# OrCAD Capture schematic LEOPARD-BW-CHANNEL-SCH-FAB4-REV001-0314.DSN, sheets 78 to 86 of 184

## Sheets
78 103_TPM HEADER: size A3; title: TPM HEADER
79 102_WELLSBURG SPI FLASH: size Custom; title: WELLSBURG SPI FLASH
80 101_miniSAS CONNECTORS_SATA_PWR: size A3; title: MiniSAS CONNECTOR_SATA_PWR
81 098_mSATA CONNECTOR: size A3; title: mSATA CONNECTOR
82 097_SATA CONNECTORS: size A3; title: SATA CONNECTOR
83 096_NGFF CONNECTOR: size Custom; title: NGFF CONNECTOR
84 095_WBG - HEADERS: size A3; title: WBG - HEADERS
85 090_WBG - FILTERING: title: WBG - FILTERING
86 089_WBG - GROUND: size A3; title: WBG - GROUND

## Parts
sheet 083_WBG - DMI & USB
WBG1  WELLSBURG-1-GP-U  [BGA836M25H87]  (sections A,B,C,D,E,F,G,H,I,J,K)
sheet 095_WBG - HEADERS
C272  SC1U10V2KX-4-GP  [C402H22]
C273  SC1U10V2KX-4-GP  [C402H22]
CN47  FCI-CON3-S1-GP  [68001-203HLF]
JP3  FCI-CON3-S1-GP  [68001-203HLF]
JP4  FCI-CON3-S1-GP  [68001-203HLF]
JP6  FCI-CON3-S1-GP  [68001-203HLF]
R233  1KR2F-3-GP  [R402H16]
R234  10KR2F-2-GP  [R402H16]
R236  100R2F-L1-GP-U  [R402H14]
R237  1KR2F-3-GP  [R402H16]
R239  20KR2F-L-GP  [R402H16]
R240  10KR2F-2-GP  [R402H16]
R241  1MR3F-GP  [R603H22]
R242  1KR2F-3-GP  [R402H16]
R243  1KR2F-3-GP  [R402H16]
R244  4K7R2F-GP  [R402H16]
R245  1MR3F-GP  [R603H22]
R246  20KR2F-L-GP  [R402H16]
R260  0R2J-2-GP  [R402H16]
R918  10KR2F-2-GP  [R402H16]
TP191  TPAD24  [TPAD24]
TP283  TPAD24  [TPAD24]
TP284  TPAD24  [TPAD24]
TP315  TPAD24  [TPAD24]
TP316  TPAD24  [TPAD24]
TP317  TPAD24  [TPAD24]
TP318  TPAD24  [TPAD24]
sheet 096_NGFF CONNECTOR
C28  SC1U10V2KX-4-GP  [C402H22]
C29  SC10U6D3V5KX-4GP  [C805H58]
C30  SC1U10V2KX-4-GP  [C402H22]
C85  SC1U10V2KX-4-GP  [C402H22]
C87  SC1U10V2KX-4-GP  [C402H22]
C90  SCD1U16V2KX-3GP  [C402H22]
C91  SCD1U16V2KX-3GP  [C402H22]
C93  SCD1U16V2KX-3GP  [C402H22]
C94  SCD1U16V2KX-3GP  [C402H22]
C103  SCD1U16V2KX-3GP  [C402H22]
C106  SC10U6D3V5KX-4GP  [C805H58]
C757  SCD01U16V2KX-3GP  [C402H22]
C758  SCD01U16V2KX-3GP  [C402H22]
NGFF1  SKT-MINI67P-33-GP  [10128798-004RLF]
R257  0R6J-3-GP  [R1206H28]
R258  0R6J-3-GP  [R1206H28]
R524  0R2J-2-GP  [R402H16]
R530  0R2J-2-GP  [R402H16]
R1041  10KR2F-2-GP  [R402H16]
R1106  0R2J-2-GP  [R402H16]
R1109  0R2J-2-GP  [R402H16]
R1207  0R2J-2-GP  [R402H16]
R1208  0R2J-2-GP  [R402H16]
R1258  0R2J-2-GP  [R402H16]
sheet 097_SATA CONNECTORS
C737  SCD01U16V2KX-3GP  [C402H22]
C738  SCD01U16V2KX-3GP  [C402H22]
C739  SCD01U16V2KX-3GP  [C402H22]
C740  SCD01U16V2KX-3GP  [C402H22]
C798  SC10U16V6KX-2GP  [C1206H71]
C1203  SCD1U16V2KX-3GP  [C402H22]
C1207  SC10U25V6KX-2GP  [C1206H63]
F2  FUSE-3A75V-GP  [FUSE-3216-2H68]
F5  FUSE-3A75V-GP  [FUSE-3216-2H68]
HDPR1  AMP-CON4-S2-GP  [171825-4]
SATA1  SKT-SATA7P-19-GP-U  [ABA-SAT-010-K04-U]
sheet 098_mSATA CONNECTOR
C310  SCD1U16V2KX-3GP  [C402H22]
C311  SCD1U16V2KX-3GP  [C402H22]
C312  SCD1U16V2KX-3GP  [C402H22]
C313  SCD1U16V2KX-3GP  [C402H22]
C753  SCD01U16V2KX-3GP  [C402H22]
C754  SCD01U16V2KX-3GP  [C402H22]
MSATA1  SKT-MINI52P-200-GP  [80003-3023]
R947  0R2J-2-GP  [R402H16]
R1038  0R2J-2-GP  [R402H16]
R1268  0R2J-2-GP  [R402H16]
sheet 101_miniSAS CONNECTORS_SATA_PWR
C1140  E100U16VM-32-GP  [ECAP-100D6D3H237]
C1142  SCD1U16V2KX-3GP  [C402H22]
C1144  SCD1U16V2KX-3GP  [C402H22]
C1145  SCD1U16V2KX-3GP  [C402H22]
C1147  SCD1U16V2KX-3GP  [C402H22]
C1148  E100U16VM-32-GP  [ECAP-100D6D3H237]
C1151  SCD1U16V2KX-3GP  [C402H22]
C1152  SCD1U16V2KX-3GP  [C402H22]
C1154  SCD1U16V2KX-3GP  [C402H22]
C1155  SCD1U16V2KX-3GP  [C402H22]
F3  FUSE-7A32V-GP  [FUSE-3216H43]
F4  FUSE-7A32V-GP  [FUSE-3216H43]
F7  FUSE-20A24V-GP  [FUSE-3216H43]
SASPW1  LOTES-CONN8B-S-GP-U1  [ABA-POW-005-K04-U1]
sheet 102_WELLSBURG SPI FLASH
C27  SCD1U16V2KX-3GP  [C402H22]
C327  SCD1U16V2KX-3GP  [C402H22]
C328  SC1U10V2KX-4-GP  [C402H22]
C357  SCD1U16V2KX-3GP  [C402H22]
C358  SCD1U16V2KX-3GP  [C402H22]
C5695  SCD1U16V2KX-3GP  [C402H22]
R301  0R2J-2-GP  [R402H16]
R304  0R2J-2-GP  [R402H16]
R305  0R2J-2-GP  [R402H16]
R306  0R2J-2-GP  [R402H16]
R307  10KR2F-2-GP  [R402H16]
R308  10KR2F-2-GP  [R402H16]
R309  0R2J-2-GP  [R402H16]
R310  0R2J-2-GP  [R402H16]
R311  0R2J-2-GP  [R402H16]
R312  33R2F-3-GP  [R402H16]
R313  33R2F-3-GP  [R402H16]
R314  1KR2F-L-GP  [R402H16]
R373  0R2J-2-GP  [R402H16]
R375  10KR2F-2-GP  [R402H16]
R376  0R2J-2-GP  [R402H16]
R377  10KR2F-L1-GP  [R402H15]
R412  10KR2F-2-GP  [R402H16]
R414  10KR2F-2-GP  [R402H16]
R427  0R2J-2-GP  [R402H16]
R432  0R2J-2-GP  [R402H16]
R434  2K2R2F-GP  [R402H16]
R464  10KR2F-2-GP  [R402H16]
R466  10KR2F-2-GP  [R402H16]
R500  2K2R2F-GP  [R402H16]
R509  10KR2F-2-GP  [R402H16]
R729  0R2J-2-GP  [R402H16]
R730  0R2J-2-GP  [R402H16]
R772  0R2J-2-GP  [R402H16]
R794  0R2J-2-GP  [R402H16]
R795  0R2J-2-GP  [R402H16]
R800  0R2J-2-GP  [R402H16]
R801  0R2J-2-GP  [R402H16]
R948  2K2R2F-GP  [R402H16]
R5846  220R2J-L2-GP  [R402H16]
SKT2  SKT-SPI16P-GP-U  [SKT-SOIC16-153139H258]
U19  NC7SB3157P6X-2GP  [UMT6H44]
U20  PI3B3257QE-GP  [QSOIC16H69]
U28  W25Q128FVFIG-GP  [SOIC16-6H104]
U106  SNLVC1G125DB-GP  [SOT-23-5H58]
U107  SNLVC1G125DB-GP  [SOT-23-5H58]
sheet 103_TPM HEADER
C31  SCD1U10V2KX-5GP  [C402H22]
C32  SCD1U10V2KX-5GP  [C402H22]
CN3  FCI-CONN15-GP  [91932-31115LF]
R1274  1KR2F-L-GP  [R402H16]
R1275  0R2J-2-GP  [R402H16]

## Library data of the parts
WBG1 = WELLSBURG-1-GP-U: IC PCH WELLSBURG FCBGA 836P(SERVER); GREENDFACTOR: R2_C;; POP?: 071.82029.0B0U; Package Type: ASIC2-G4; Part Number: 71.WSBUG.00U; SPEC: http://wpqssvr.wistron.com.tw:7001/wpqs/servlet/COM.qpart.Attachment?PartNumber=71.WSBUG.00U
C28 C30 C85 C87 C272 C273 C328 = SC1U10V2KX-4-GP: CHIP CAP C 1U 10V K 0402 X6S; GREENDFACTOR: R2_SA;HF_SA;; Part Number: 78.10523.8FL; Part Type: SMD-BCG6; SPEC: http://wpqssvr.wistron.com.tw:7001/wpqs/servlet/COM.qpart.Attachment?PartNumber=78.10523.8FL
CN47 = FCI-CON3-S1-GP: HEAD ML 1R3P ST 68001-203HLF; Category: PCH; GREENDFACTOR: R_SA;; Green Factor: R_SA;; Part Number: 21.61084.103; Part Type: CONN-G4; ROOM: IMMv2; S/D: DIP; SPEC: http://wpqssvr.wistron.com.tw:7001/wpqs/servlet/COM.qpart.Attachment?PartNumber=21.61084.103; Vender: FCI
JP3 JP4 JP6 = FCI-CON3-S1-GP: HEAD ML 1R3P ST 68001-203HLF; GREENDFACTOR: R2_SA;; Part Number: 21.61084.103; Part Type: CONN-G4; SPEC: http://wpqssvr.wistron.com.tw:7001/wpqs/servlet/COM.qpart.Attachment?PartNumber=21.61084.103
R233 R237 R242 = 1KR2F-3-GP: CHIP RES 1K F 1/16W 0402; Category: PCH; GREENDFACTOR: R2_SA;HF_SA;G_SA;; Package Type: SMD-RG; Part Number: 64.10015.6DL; Part Type: SMD-RG; SPEC: http://wpqssvr.wistron.com.tw:7001/wpqs/servlet/COM.qpart.Attachment?PartNumber=64.10015.6DL; VENDORPARTNUMBER: RM04FTN1001 / RTT021001FTH / RR0510S-1001-FN / RC0402FR-071KL/WR04X1001FTL
R234 R240 R307 R308 R375 R412 R414 R509 = 10KR2F-2-GP: CHIP RES 10K F 1/16W 0402; GREENDFACTOR: R2_SA;HF_SA;G_SA;; Part Number: 64.10025.6DL; Part Type: SMD-RG; SPEC: http://wpqssvr.wistron.com.tw:7001/wpqs/servlet/COM.qpart.Attachment?PartNumber=64.10025.6DL
R236 = 100R2F-L1-GP-U: CHIP RES 100 F 1/16W 0402; Category: CPU SIDE BAND; POP?: NOPOP; Part Number: 64.10005.6DL; Part Type: SMD-RG
R239 R246 = 20KR2F-L-GP: CHIP RES 20K F 1/16W 0402; GREENDFACTOR: R2_SA;HF_SA;G_SA;; Package Type: SMD-RG; Part Number: 64.20025.6DL; SPEC: http://wpqssvr.wistron.com.tw:7001/wpqs/servlet/COM.qpart.Attachment?PartNumber=64.20025.6DL
R241 = 1MR3F-GP: CHIP RES 1M F 1/10W 0603(ROHS); Category: PCH; Part Number: 64.10045.55L; Part Type: RCL_GP
R243 = 1KR2F-3-GP: CHIP RES 1K F 1/16W 0402; Category: PCH; GREENDFACTOR: R2_SA;HF_SA;G_SA;; POP?: NOPOP; Package Type: SMD-RG; Part Number: 64.10015.6DL; Part Type: SMD-RG; SPEC: http://wpqssvr.wistron.com.tw:7001/wpqs/servlet/COM.qpart.Attachment?PartNumber=64.10015.6DL; VENDORPARTNUMBER: RM04FTN1001 / RTT021001FTH / RR0510S-1001-FN / RC0402FR-071KL/WR04X1001FTL
R244 = 4K7R2F-GP: CHIP RES 4.7K F 1/16W 0402; Category: PCH; Part Number: 64.47015.6DL; Part Type: RCL_GP
R245 = 1MR3F-GP: CHIP RES 1M F 1/10W 0603(ROHS); Category: PCH; POP?: NOPOP; Part Number: 64.10045.55L; Part Type: RCL_GP
R260 R301 R304-R306 R373 R376 R427 R432 = 0R2J-2-GP: CHIP RES 0 J 1/16W 0402; Category: PCH; DESCRIPTIO: CHIP RES 0 J 1/16W 0402; GREENDFACTOR: R2_SA;HF_SA;G_SA;; POP?: NOPOP; Package Type: SMD-RG; Part Number: 63.R0034.1DL; Part Type: SMD-RG; SPEC: http://wpqssvr.wistron.com.tw:7001/wpqs/servlet/COM.qpart.Attachment?PartNumber=63.R0034.1DL; VENDORPARTNUMBER: RM04JTN0/RTT02000JTH/RR0510X-000-XN/RC0402JR-070RL/WR04X000 PTL
R918 = 10KR2F-2-GP: CHIP RES 10K F 1/16W 0402; Category: PCH; DESCRIPTIO: CHIP RES 10K F 1/16W 0402; GREENDFACTOR: R2_SA;HF_SA;G_SA;; Package Type: SMD-RG; Part Number: 64.10025.6DL; Part Type: SMD-RG; SPEC: http://wpqssvr.wistron.com.tw:7001/wpqs/servlet/COM.qpart.Attachment?PartNumber=64.10025.6DL; VENDORPARTNUMBER: RM04FTN1002 / RTT021002FTH / RR0510S-103-FN / RC0402FR-0710KL/WR04X1002FTL
TP191 TP283 TP284 TP315-TP318 = TPAD24: 24 MILS TEST PAD; Category: PCH; Part Number: ZZ.PAD24.001; Part Type: DISCRET2
C29 C106 = SC10U6D3V5KX-4GP: CHIP CAP C 10U 6.3V K0805 X7R; GREENDFACTOR: R2_SA;HF_SA;G_SA;; Package Type: SMD-BCG; Part Number: 78.10620.21L; Part Type: SMD-BCG; SPEC: http://wpqssvr.wistron.com.tw:7001/wpqs/servlet/COM.qpart.Attachment?PartNumber=78.10620.21L
C90 C91 C93 C94 C103 = SCD1U16V2KX-3GP: CHIP CAP C 0.1U 16V K0402 X7R; CATEGORIES: CAP_1.xV; GREENDFACTOR: R2_SA;HF_SA;G_SA;; MAIN_SOURCE: M; Package Type: SMD-BCG; Part Number: 78.10421.2FL; Part Type: SMD-BCG; SPEC: http://wpqssvr.wistron.com.tw:7001/wpqs/servlet/COM.qpart.Attachment?PartNumber=78.10421.2FL
C757 C758 = SCD01U16V2KX-3GP: CHIP CAP0.01U16V K0402 X7R(ROH; Category: PCH; POP?: NOPOP; Part Number: 78.10321.2FL; Part Type: SMD-BCG
NGFF1 = SKT-MINI67P-33-GP: SKT MINI PCIE/SATA M.2 10128798-004RLF; GREENDFACTOR: R2_C;; POP?: NOPOP; Part Number: 062.10007.0651; Part Type: SOCKET-G4; SPEC: http://wpqssvr.wistron.com.tw:7001/wpqs/servlet/COM.qpart.Attachment?PartNumber=062.10007.0651
R257 = 0R6J-3-GP: CHIP RES 0 J 1/4W 1206 (ROHS); GREENDFACTOR: R2_SA;HF_SA;G_SA;; Part Number: 63.R0032.11L; Part Type: SMD-RG; SPEC: http://wpqssvr.wistron.com.tw:7001/wpqs/servlet/COM.qpart.Attachment?PartNumber=63.R0032.11L
R258 = 0R6J-3-GP: CHIP RES 0 J 1/4W 1206 (ROHS); GREENDFACTOR: R2_SA;HF_SA;G_SA;; POP?: NOPOP; Part Number: 63.R0032.11L; Part Type: SMD-RG; SPEC: http://wpqssvr.wistron.com.tw:7001/wpqs/servlet/COM.qpart.Attachment?PartNumber=63.R0032.11L
R524 = 0R2J-2-GP: CHIP RES 0 J 1/16W 0402; Category: N1 DIMM; GREENDFACTOR: R2_SA;HF_SA;G_SA;; POP?: NOPOP; Package Type: SMD-RG; Part Number: 63.R0034.1DL; Part Type: SMD-RG; SPEC: http://wpqssvr.wistron.com.tw:7001/wpqs/servlet/COM.qpart.Attachment?PartNumber=63.R0034.1DL
R530 R1258 = 0R2J-2-GP: CHIP RES 0 J 1/16W 0402; Category: N1 BMC; GREENDFACTOR: R2_SA;HF_SA;G_SA;; POP?: NOPOP; Part Number: 63.R0034.1DL; Part Type: SMD-RG; SPEC: http://wpqssvr.wistron.com.tw:7001/wpqs/servlet/COM.qpart.Attachment?PartNumber=63.R0034.1DL
R1041 = 10KR2F-2-GP: CHIP RES 10K F 1/16W 0402; Category: PCH; DESCRIPTIO: CHIP RES 10K F 1/16W 0402; GREENDFACTOR: R2_SA;HF_SA;G_SA;; POP?: NOPOP; Package Type: SMD-RG; Part Number: 64.10025.6DL; Part Type: SMD-RG; SPEC: http://wpqssvr.wistron.com.tw:7001/wpqs/servlet/COM.qpart.Attachment?PartNumber=64.10025.6DL; VENDORPARTNUMBER: RM04FTN1002 / RTT021002FTH / RR0510S-103-FN / RC0402FR-0710KL/WR04X1002FTL
R730 R1106 R1109 R1207 R1208 = 0R2J-2-GP: CHIP RES 0 J 1/16W 0402; GREENDFACTOR: R2_SA;HF_SA;G_SA;; POP?: NOPOP; Package Type: SMD-RG; Part Number: 63.R0034.1DL; SPEC: http://wpqssvr.wistron.com.tw:7001/wpqs/servlet/COM.qpart.Attachment?PartNumber=63.R0034.1DL
C737-C740 = SCD01U16V2KX-3GP: CHIP CAP0.01U16V K0402 X7R(ROH; Belong: POP; Category: SATA; Part Number: 78.10321.2FL; Part Type: SMD-BCG
C798 = SC10U16V6KX-2GP: CHIP CAP C 10U 16V K1206 X7R; Category: SATA; GREENDFACTOR: R2_SA;HF_SA;G_SA;; Part Number: 78.10621.22L; Part Type: SMD-BCG; SPEC: http://wpqssvr.wistron.com.tw:7001/wpqs/servlet/COM.qpart.Attachment?PartNumber=78.10621.22L
C1203 = SCD1U16V2KX-3GP: CHIP CAP C 0.1U 16V K0402 X7R; Belong: POP; CATEGORIES: CAP_1.xV; Category: SATA; GREENDFACTOR: R2_SA;HF_SA;G_SA;; MAIN_SOURCE: M; Part Number: 78.10421.2FL; Part Type: SMD-BCG; SPEC: http://wpqssvr.wistron.com.tw:7001/wpqs/servlet/COM.qpart.Attachment?PartNumber=78.10421.2FL
C1207 = SC10U25V6KX-2GP: CHIP CAP C 10U 25V K1206 X6S; GREENDFACTOR: R2_SA;HF_SA;; Part Number: 78.10622.82L; Part Type: SMD-BCG; SPEC: http://wpqssvr.wistron.com.tw:7001/wpqs/servlet/COM.qpart.Attachment?PartNumber=78.10622.82L
F2 F5 = FUSE-3A75V-GP: CHIP FUSE 3A 75V 0458003.DR; GREENDFACTOR: R2_SA;HF_SA;; Part Number: 69.43001.511; Part Type: DISCRET-G5; SPEC: http://wpqssvr.wistron.com.tw:7001/wpqs/servlet/COM.qpart.Attachment?PartNumber=69.43001.511
HDPR1 = AMP-CON4-S2-GP: HEAD ML 1R4P ST D2.5 1S L7.5; Category: SATA; GREENDFACTOR: R2_SA;; Part Number: 21.60409.104; Part Type: CONN-G5; SPEC: http://wpqssvr.wistron.com.tw:7001/wpqs/servlet/COM.qpart.Attachment?PartNumber=21.60409.104
SATA1 = SKT-SATA7P-19-GP-U: CONN CTR 7P ABA-SAT-010-K02 BLACK 15U"; GREENDFACTOR: R2_SA;; Part Number: 20.81112.007; Part Type: SOCKET-G2; SPEC: http://wpqssvr.wistron.com.tw:7001/wpqs/servlet/COM.qpart.Attachment?PartNumber=20.81112.007
C310-C313 = SCD1U16V2KX-3GP: CHIP CAP C 0.1U 16V K0402 X7R; CATEGORIES: CAP_1.xV; GREENDFACTOR: R2_SA;HF_SA;G_SA;; MAIN_SOURCE: M; Package Type: SMD-BCG; Part Number: 78.10421.2FL; SPEC: http://wpqssvr.wistron.com.tw:7001/wpqs/servlet/COM.qpart.Attachment?PartNumber=78.10421.2FL
C753 C754 = SCD01U16V2KX-3GP: CHIP CAP0.01U16V K0402 X7R(ROH; Category: PCH; Part Number: 78.10321.2FL; Part Type: SMD-BCG
MSATA1 = SKT-MINI52P-200-GP: SKT MINI PCI 52P 80003-3023 SMD ,LCP; GREENDFACTOR: R2_C;; Part Number: 062.10007.0181; Part Type: SOCKET-G2; SPEC: http://wpqssvr.wistron.com.tw:7001/wpqs/servlet/COM.qpart.Attachment?PartNumber=062.10007.0181
R309-R311 R729 R772 R794 R795 R800 R801 R947 R1038 = 0R2J-2-GP: CHIP RES 0 J 1/16W 0402; GREENDFACTOR: R2_SA;HF_SA;G_SA;; Package Type: SMD-RG; Part Number: 63.R0034.1DL; SPEC: http://wpqssvr.wistron.com.tw:7001/wpqs/servlet/COM.qpart.Attachment?PartNumber=63.R0034.1DL
R1268 = 0R2J-2-GP: CHIP RES 0 J 1/16W 0402; Category: N1 BMC; GREENDFACTOR: R2_SA;HF_SA;G_SA;; Part Number: 63.R0034.1DL; Part Type: SMD-RG; SPEC: http://wpqssvr.wistron.com.tw:7001/wpqs/servlet/COM.qpart.Attachment?PartNumber=63.R0034.1DL
C1140 C1148 = E100U16VM-32-GP: CAP EL 100U16V RT2.5 6.3*6 OS; Category: PWRI/O CONN; GREENDFACTOR: R2_SA;HF_SA;G_SA;; Part Number: 09.1071D.25L; Part Type: DIP-TCG3; SPEC: http://wpqssvr.wistron.com.tw:7001/wpqs/servlet/COM.qpart.Attachment?PartNumber=09.1071D.25L
C1142 C1144 C1145 C1147 C1151 C1152 C1154 C1155 = SCD1U16V2KX-3GP: CHIP CAP C 0.1U 16V K0402 X7R; Belong: POP; CATEGORIES: CAP_1.xV; Category: PWRI/O CONN; GREENDFACTOR: R2_SA;HF_SA;G_SA;; MAIN_SOURCE: M; Part Number: 78.10421.2FL; Part Type: SMD-BCG; SPEC: http://wpqssvr.wistron.com.tw:7001/wpqs/servlet/COM.qpart.Attachment?PartNumber=78.10421.2FL
F3 F4 = FUSE-7A32V-GP: CHIP FUSE 7A 32V 3216FF7-R; Belong: POP; Category: PWRI/O CONN; GREENDFACTOR: R_SA;; Module: PCIE SLOT; Package Type: DISCRET-G4; Part Number: 69.47001.091; SPEC: http://wpqssvr.wistron.com.tw:7001/wpqs/servlet/COM.qpart.Attachment?PartNumber=69.47001.091
F7 = FUSE-20A24V-GP: CHIP FUSE 20A 24V CC12M20A; GREENDFACTOR: R2_SA;HF_SA;; Part Number: 69.42002.021; Part Type: DISCRET-G6; SPEC: http://wpqssvr.wistron.com.tw:7001/wpqs/servlet/COM.qpart.Attachment?PartNumber=69.42002.021
SASPW1 = LOTES-CONN8B-S-GP-U1: CONN CTR 8P ABA-POW-005-K04; GREENDFACTOR: R2_C;; Part Number: 20.82029.008; Part Type: CONN-G2; SPEC: http://wpqssvr.wistron.com.tw:7001/wpqs/servlet/COM.qpart.Attachment?PartNumber=20.82029.008
C27 C5695 = SCD1U16V2KX-3GP: CHIP CAP C 0.1U 16V K0402 X7R; CATEGORIES: CAP_1.xV; GREENDFACTOR: R2_SA;HF_SA;G_SA;; MAIN_SOURCE: M; Part Number: 78.10421.2FL; Part Type: SMD-BCG; SPEC: http://wpqssvr.wistron.com.tw:7001/wpqs/servlet/COM.qpart.Attachment?PartNumber=78.10421.2FL
C327 C357 C358 = SCD1U16V2KX-3GP: CHIP CAP C 0.1U 16V K0402 X7R; Category: PCH; GREENDFACTOR: R_SA;HF_SA;G_SA;; Part Number: 78.10421.2FL; Quotation: 12_14; Type: SMD
R312 R313 = 33R2F-3-GP: CHIP RES 33 F 1/16W 0402(ROHS); Category: PCH; Part Number: 64.33R05.6DL; Part Type: SMD-RG
R314 = 1KR2F-L-GP: CHIP RES 1K F 1/16W 0402; GREENDFACTOR: R2_SA;HF_SA;G_SA;; Package Type: SMD-RG2; Part Number: 64.10015.L1L; SPEC: http://wpqssvr.wistron.com.tw:7001/wpqs/servlet/COM.qpart.Attachment?PartNumber=64.10015.L1L
R377 = 10KR2F-L1-GP: CHIP RES 10K F 1/16W 0402 13" REEL; Category: PCH; POP?: NOPOP; Part Number: 64.10025.L0L; Part Type: SMD-RG5
R434 R500 = 2K2R2F-GP: CHIP RES 2.2K F 1/16W 0402; GREENDFACTOR: R2_SA;HF_SA;G_SA;; Package Type: RCL_GP; Part Number: 64.22015.6DL; SPEC: http://wpqssvr.wistron.com.tw:7001/wpqs/servlet/COM.qpart.Attachment?PartNumber=64.22015.6DL
R464 R466 = 10KR2F-2-GP: CHIP RES 10K F 1/16W 0402; GREENDFACTOR: R2_SA;HF_SA;G_SA;; POP?: NOPOP; Part Number: 64.10025.6DL; Part Type: SMD-RG; SPEC: http://wpqssvr.wistron.com.tw:7001/wpqs/servlet/COM.qpart.Attachment?PartNumber=64.10025.6DL
R948 = 2K2R2F-GP: CHIP RES 2.2K F 1/16W 0402; GREENDFACTOR: R2_SA;HF_SA;G_SA;; POP?: NOPOP; Package Type: RCL_GP; Part Number: 64.22015.6DL; SPEC: http://wpqssvr.wistron.com.tw:7001/wpqs/servlet/COM.qpart.Attachment?PartNumber=64.22015.6DL
R5846 = 220R2J-L2-GP: CHIP RES 220 J 1/16W 0402; Category: PCH; GREENDFACTOR: R2_SA;HF_SA;G_SA;; Package Type: SMD-RG; Part Number: 63.22134.1DL; Part Type: SMD-RG; SPEC: http://wpqssvr.wistron.com.tw:7001/wpqs/servlet/COM.qpart.Attachment?PartNumber=63.22134.1DL
SKT2 = SKT-SPI16P-GP-U: SKT SPI CONN ACA-SPI-006-K01 ,LCP; GREENDFACTOR: R2_SA;HF_SA;; Part Number: 62.10089.021; Part Type: SOCKET-G2; SPEC: http://wpqssvr.wistron.com.tw:7001/wpqs/servlet/COM.qpart.Attachment?PartNumber=62.10089.021
U19 = NC7SB3157P6X-2GP: IC SW NC7SB3157P6X SC70(L/F); Alternate: 73.03157.B0H; Category: XDP; DESCRIPTIO: IC SW NC7SB3157P6X SC70(L/F); GREENDFACTOR: R2_SA;; Note: The same as CRB; Package Type: DISCRET-G; Part Number: 73.03157.D0H; Part Type: DISCRET-G; SPEC: http://wpqssvr.wistron.com.tw:7001/wpqs/servlet/COM.qpart.Attachment?PartNumber=73.03157.D0H; VENDORPARTNUMBER: NC7SB3157P6X
U20 = PI3B3257QE-GP_0: IC BUS SW PI3B3257QE QSOP 16P; 2nd source: 73.03257.A0C; 3rd source: 73.03257.F0C; Category: PCH; GREENDFACTOR: R_SA;; Package Type: DISCRET-G2; Part Number: 73.33257.A0C; Part Type: DISCRET-G2; SPEC: http://wpqssvr.wistron.com.tw:7001/wpqs/servlet/COM.qpart.Attachment?PartNumber=73.33257.A0C
U28 = W25Q128FVFIG-GP: IC FEROM W25Q128FVFIG SOIC 16P; GREENDFACTOR: R2_SA;; Part Number: 72.00128.011; Part Type: MEMORY-G4; SPEC: http://wpqssvr.wistron.com.tw:7001/wpqs/servlet/COM.qpart.Attachment?PartNumber=72.00128.011
U106 U107 = SNLVC1G125DB-GP: IC CMOS SN74LVC1G125DBVR SOT23; Category: UID LED; GREENDFACTOR: R2_SA;HF_SA;; Package Type: TTL-G; Part Number: 73.1G125.AHG; SPEC: http://wpqssvr.wistron.com.tw:7001/wpqs/servlet/COM.qpart.Attachment?PartNumber=73.1G125.AHG
C31 C32 = SCD1U10V2KX-5GP: CHIP CAP C 0.1U 10V K0402 X7R; CATEGORIES: CAP_1.xV; GREENDFACTOR: R2_SA;HF_SA;G_SA;; MAIN_SOURCE: M; Part Number: 78.10423.2FL; Part Type: SMD-BCG; SPEC: http://wpqssvr.wistron.com.tw:7001/wpqs/servlet/COM.qpart.Attachment?PartNumber=78.10423.2FL
CN3 = FCI-CONN15-GP: CONN CTR SMD 15P 91932-31115LF , LCP; GREENDFACTOR: R2_C;; Part Number: 020.F0007.0015; Part Type: CONN-G6; SPEC: http://wpqssvr.wistron.com.tw:7001/wpqs/servlet/COM.qpart.Attachment?PartNumber=020.F0007.0015
R1274 = 1KR2F-L-GP: CHIP RES 1K F 1/16W 0402; Category: CPU SIDE BAND; POP?: NOPOP; Part Number: 64.10015.L1L; Part Type: SMD-RG2
R1275 = 0R2J-2-GP: CHIP RES 0 J 1/16W 0402; Category: PCH; DESCRIPTIO: CHIP RES 0 J 1/16W 0402; GREENDFACTOR: R2_SA;HF_SA;G_SA;; Package Type: SMD-RG; Part Number: 63.R0034.1DL; Part Type: SMD-RG; SPEC: http://wpqssvr.wistron.com.tw:7001/wpqs/servlet/COM.qpart.Attachment?PartNumber=63.R0034.1DL; VENDORPARTNUMBER: RM04JTN0/RTT02000JTH/RR0510X-000-XN/RC0402JR-070RL/WR04X000 PTL

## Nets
GND: C27.2 C28.2 C29.2 C30.2 C31.2 C32.2 C85.2 C87.2 C90.2 C91.2 C93.2 C94.2 C103.2 C106.2 C272.2 C273.2 C310.2 C311.2 C312.2 C313.2 C327.2 C328.2 C357.2 C358.2 C798.2 C1140.2 C1142.1 C1144.1 C1145.1 C1147.1 C1148.2 C1151.1 C1152.1 C1154.1 C1155.1 C1203.2 C1207.2 C5695.2 CN3.13 CN3.14 CN3.G1 CN3.G2 CN47.3 HDPR1.2 HDPR1.3 MSATA1.4 MSATA1.9 MSATA1.15 MSATA1.18 MSATA1.21 MSATA1.26 MSATA1.27 MSATA1.29 MSATA1.34 MSATA1.35 MSATA1.37 MSATA1.40 MSATA1.43 MSATA1.50 MSATA1.53 MSATA1.54 NGFF1.1 NGFF1.3 NGFF1.9 NGFF1.15 NGFF1.21 NGFF1.27 NGFF1.33 NGFF1.39 NGFF1.45 NGFF1.51 NGFF1.57 NGFF1.71 NGFF1.73 NGFF1.75 NGFF1.76 NGFF1.77 R236.2 R237.2 R242.2 R243.2 R244.2 R245.2 R260.1 R314.2 R375.2 R509.2 R1041.2 R1274.2 R5846.2 SASPW1.1 SASPW1.2 SASPW1.3 SASPW1.4 SATA1.1 SATA1.4 SATA1.7 SATA1.8 SATA1.9 SKT2.10 TP318.1 U19.2(GND) U20.8(GND) U28.10(GND) U106.3(GND) U107.3(GND) WBG1.A4(VSS) WBG1.A5(VSS) WBG1.A7(VSS) WBG1.A11(VSS) WBG1.A15(VSS) WBG1.A19(VSS) WBG1.A23(VSS) WBG1.A27(VSS) WBG1.A29(VSS) WBG1.A31(VSS) WBG1.A35(VSS) WBG1.A39(VSS) WBG1.A43(VSS) WBG1.A45(VSS) WBG1.A46(VSS) WBG1.A48(VSS) WBG1.AA1(VSS) WBG1.AA3(VSS) WBG1.AA10(VSS) WBG1.AA43(VSS) WBG1.AA44(VSS) WBG1.AB46(VSS) WBG1.AC3(VSS) WBG1.AC6(VSS) WBG1.AC10(VSS) WBG1.AC49(VSS) WBG1.AD18(VSS) WBG1.AD19(VSS) WBG1.AD21(VSS) WBG1.AD23(VSS) WBG1.AD24(VSS) WBG1.AD26(VSS) WBG1.AD27(VSS) WBG1.AD29(VSS) WBG1.AD31(VSS) WBG1.AD32(VSS) WBG1.AE1(VSS) WBG1.AE3(VSS) WBG1.AE6(VSS) WBG1.AE9(VSS) WBG1.AE12(VSS) WBG1.AE15(VSS) WBG1.AE35(VSS) WBG1.AE38(VSS) WBG1.AE41(VSS) WBG1.AE44(VSS) WBG1.AF46(VSS) WBG1.AG1(VSS) WBG1.AG3(VSS) WBG1.AG47(VSS) WBG1.AG49(VSS) WBG1.AH48(VSS) WBG1.AJ1(VSS) WBG1.AJ3(VSS) WBG1.AJ6(VSS) WBG1.AJ7(VSS) WBG1.AJ9(VSS) WBG1.AJ10(VSS) WBG1.AJ12(VSS) WBG1.AJ14(VSS) WBG1.AJ19(VSS) WBG1.AJ21(VSS) WBG1.AJ23(VSS) WBG1.AJ24(VSS) WBG1.AJ26(VSS) WBG1.AJ27(VSS) WBG1.AJ31(VSS) WBG1.AJ38(VSS) WBG1.AK6(VSS) WBG1.AK9(VSS) WBG1.AK12(VSS) WBG1.AK15(VSS) WBG1.AK35(VSS) WBG1.AK38(VSS) WBG1.AK41(VSS) WBG1.AK44(VSS) WBG1.AK46(VSS) WBG1.AL1(VSS) WBG1.AL3(VSS) WBG1.AL49(VSS) WBG1.AM9(VSS) WBG1.AM14(VSS) WBG1.AM15(VSS) WBG1.AM18(VSS) WBG1.AM19(VSS) WBG1.AM21(VSS) WBG1.AM27(VSS) WBG1.AM29(VSS) WBG1.AM31(VSS) WBG1.AM32(VSS) WBG1.AM38(VSS) WBG1.AN1(VSS) WBG1.AN3(VSS) WBG1.AP6(VSS) WBG1.AP10(VSS) WBG1.AP15(VSS) WBG1.AP31(VSS) WBG1.AP35(VSS) WBG1.AP38(VSS) WBG1.AP46(VSS) WBG1.AR1(VSS) WBG1.AR3(VSS) WBG1.AR49(VSS) WBG1.AT6(VSS) WBG1.AT9(VSS) WBG1.AT12(VSS) WBG1.AT15(VSS) WBG1.AT35(VSS) WBG1.AT38(VSS) WBG1.AT41(VSS) WBG1.AT44(VSS) WBG1.AT48(VSS) WBG1.AU1(VSS) WBG1.AU3(VSS) WBG1.AU9(VSS) WBG1.AU14(VSS) WBG1.AU35(VSS) WBG1.AU36(VSS) WBG1.AU38(VSS) WBG1.AU40(VSS) WBG1.AU41(VSS) WBG1.AU47(VSS) WBG1.AU49(VSS) WBG1.AV18(VSS) WBG1.AV20(VSS) WBG1.AV21(VSS) WBG1.AV23(VSS) WBG1.AV25(VSS) WBG1.AV30(VSS) WBG1.AW1(VSS) WBG1.AW3(VSS) WBG1.AW16(VSS) WBG1.AW18(VSS) WBG1.AW21(VSS) WBG1.AW27(VSS) WBG1.AW29(VSS) WBG1.AW38(VSS) WBG1.AW43(VSS) WBG1.AW47(VSS) WBG1.AW49(VSS) WBG1.B2(VSS) WBG1.B22(VSS) WBG1.B48(VSS) WBG1.B49(VSS) WBG1.BA1(VSS) WBG1.BA3(VSS) WBG1.BA9(VSS) WBG1.BA14(VSS) WBG1.BA16(VSS) WBG1.BA20(VSS) WBG1.BA21(VSS) WBG1.BA25(VSS) WBG1.BA27(VSS) WBG1.BA29(VSS) WBG1.BA30(VSS) WBG1.BA32(VSS) WBG1.BA36(VSS) WBG1.BA38(VSS) WBG1.BA41(VSS) WBG1.BA43(VSS) WBG1.BA47(VSS) WBG1.BA49(VSS) WBG1.BC1(VSS) WBG1.BC3(VSS) WBG1.BC12(VSS) WBG1.BC27(VSS) WBG1.BC39(VSS) WBG1.BC44(VSS) WBG1.BC47(VSS) WBG1.BC49(VSS) WBG1.BD6(VSS) WBG1.BD9(VSS) WBG1.BD12(VSS) WBG1.BD14(VSS) WBG1.BD18(VSS) WBG1.BD20(VSS) WBG1.BD25(VSS) WBG1.BD27(VSS) WBG1.BD30(VSS) WBG1.BD34(VSS) WBG1.BD36(VSS) WBG1.BD39(VSS) WBG1.BD41(VSS) WBG1.BD44(VSS) WBG1.BE1(VSS) WBG1.BE49(VSS) WBG1.BF1(VSS) WBG1.BF4(VSS) WBG1.BF18(VSS) WBG1.BF44(VSS) WBG1.BF46(VSS) WBG1.BF48(VSS) WBG1.BF49(VSS) WBG1.BG7(VSS) WBG1.BG9(VSS) WBG1.BG11(VSS) WBG1.BG13(VSS) WBG1.BG15(VSS) WBG1.BG17(VSS) WBG1.BG19(VSS) WBG1.BG21(VSS) WBG1.BG23(VSS) WBG1.BG25(VSS) WBG1.BG27(VSS) WBG1.BG29(VSS) WBG1.BG31(VSS) WBG1.BG33(VSS) WBG1.BG35(VSS) WBG1.BG37(VSS) WBG1.BG39(VSS) WBG1.BG41(VSS) WBG1.BG43(VSS) WBG1.BH1(VSS) WBG1.BH2(VSS) WBG1.BH4(VSS) WBG1.BH18(VSS) WBG1.BH48(VSS) WBG1.BH49(VSS) WBG1.BJ2(VSS) WBG1.BJ4(VSS) WBG1.BJ5(VSS) WBG1.BJ7(VSS) WBG1.BJ9(VSS) WBG1.BJ11(VSS) WBG1.BJ13(VSS) WBG1.BJ15(VSS) WBG1.BJ19(VSS) WBG1.BJ23(VSS) WBG1.BJ25(VSS) WBG1.BJ31(VSS) WBG1.BJ35(VSS) WBG1.BJ39(VSS) WBG1.BJ41(VSS) WBG1.BJ43(VSS) WBG1.BJ46(VSS) WBG1.BJ48(VSS) WBG1.C7(VSS) WBG1.C9(VSS) WBG1.C11(VSS) WBG1.C13(VSS) WBG1.C15(VSS) WBG1.C17(VSS) WBG1.C19(VSS) WBG1.C21(VSS) WBG1.C23(VSS) WBG1.D1(VSS) WBG1.D2(VSS) WBG1.D22(VSS) WBG1.D24(VSS) WBG1.D28(VSS) WBG1.D32(VSS) WBG1.D36(VSS) WBG1.D40(VSS) WBG1.D44(VSS) WBG1.D49(VSS) WBG1.E1(VSS) WBG1.E49(VSS) WBG1.F9(VSS) WBG1.F14(VSS) WBG1.F16(VSS) WBG1.F20(VSS) WBG1.F23(VSS) WBG1.F25(VSS) WBG1.F30(VSS) WBG1.F36(VSS) WBG1.F41(VSS) WBG1.F46(VSS) WBG1.G1(VSS) WBG1.G3(VSS) WBG1.G16(VSS) WBG1.G49(VSS) WBG1.J1(VSS) WBG1.J3(VSS) WBG1.J9(VSS) WBG1.J14(VSS) WBG1.J20(VSS) WBG1.J30(VSS) WBG1.J36(VSS) WBG1.J41(VSS) WBG1.K46(VSS) WBG1.L1(VSS) WBG1.L3(VSS) WBG1.L7(VSS) WBG1.L49(VSS) WBG1.M20(VSS) WBG1.M25(VSS) WBG1.M30(VSS) WBG1.M32(VSS) WBG1.N1(VSS) WBG1.N3(VSS) WBG1.N32(VSS) WBG1.P6(VSS) WBG1.P9(VSS) WBG1.P12(VSS) WBG1.P15(VSS) WBG1.P35(VSS) WBG1.P38(VSS) WBG1.P41(VSS) WBG1.P44(VSS) WBG1.P46(VSS) WBG1.R1(VSS) WBG1.R3(VSS) WBG1.R49(VSS) WBG1.T6(VSS) WBG1.T10(VSS) WBG1.T48(VSS) WBG1.U1(VSS) WBG1.U3(VSS) WBG1.U47(VSS) WBG1.V14(VSS) WBG1.V46(VSS) WBG1.W1(VSS) WBG1.W3(VSS) WBG1.W18(VSS) WBG1.W19(VSS) WBG1.W23(VSS) WBG1.W24(VSS) WBG1.W26(VSS) WBG1.W27(VSS) WBG1.W31(VSS) WBG1.W32(VSS) WBG1.W47(VSS) WBG1.W49(VSS) WBG1.Y6(VSS) WBG1.Y9(VSS) WBG1.Y12(VSS) WBG1.Y15(VSS) WBG1.Y38(VSS) WBG1.Y41(VSS) WBG1.Y44(VSS) ; also on sheet 1 2 3 4 5 6 7 8 9 10 11 12 13 14 15 16 17 18 19 20 21 22 23 24 25 26 27 28 29 30 31 32 33 34 35 36 37 38 39 44 46 47 49 50 51 52 53 54 55 56 57 58 59 60 61 62 63 64 65 66 69 70 71 73 74 75 76 87 88 89 90 91 92 93 94 95 96 97 98 99 100 101 102 103 104 105 106 107 108 109 110 111 112 113 114 115 116 117 118 119 128 129 138 139 159 160 161 166 168 169 170 171 172 173 174 175 176 177 180 181 182 183 184
P3V3: C31.1 C32.1 CN3.9 R233.1 R258.2 ; also on sheet 1 3 8 45 46 48 49 52 54 58 65 74 76 87 90 91 94 95 96 100 101 102 161 166 168 173 174 177 180 181 182 183
P3V3_NGFF_MSATA: C28.1 C29.1 C30.1 C85.1 C87.1 C90.1 C91.1 C93.1 C94.1 C103.1 C106.1 C310.1 C311.1 C312.1 C313.1 MSATA1.2 MSATA1.24 MSATA1.39 MSATA1.41 MSATA1.52 NGFF1.2 NGFF1.4 NGFF1.12 NGFF1.14 NGFF1.16 NGFF1.18 NGFF1.70 NGFF1.72 NGFF1.74 R257.1 R258.1
P3V3_STBY: C27.1 C327.1 C328.1 C357.1 C358.1 C5695.1 R234.1 R240.1 R257.2 R307.1 R308.1 R377.1 R412.1 R414.1 R434.1 R464.1 R466.1 R500.1 R918.1 R948.1 SKT2.2 U19.5(VCC) U20.16(VCC) U28.2(VCC) U106.5(VCC) U107.5(VCC) ; also on sheet 2 3 5 6 8 9 10 11 12 15 16 17 20 21 22 25 26 27 30 31 33 34 35 37 38 39 45 47 49 50 51 52 54 55 59 60 61 62 63 64 65 66 69 70 71 72 73 74 76 87 88 89 90 91 92 93 94 95 96 97 98 99 159 161 166 168 173 174 176 177 179 180 182 183 184
P3V_BAT: R239.1 R241.1 R246.1 ; also on sheet 87 173 174 184
P5V: F3.1 F4.1 F5.1 ; also on sheet 45 59 66 69 76 176
P5V_HDD: C1140.1 C1148.1 C1151.2 C1152.2 C1154.2 C1155.2 F3.2 F4.2 SASPW1.5 SASPW1.7
P5V_HDPR1: C798.1 C1203.1 F5.2 HDPR1.1
P12V_HDD: C1142.2 C1144.2 C1145.2 C1147.2 F7.2 SASPW1.6 SASPW1.8
P12V_HDD_HDPR1: C1207.1 F2.2 HDPR1.4
P12V_PCIE_HDD: F2.1 F7.1 ; also on sheet 59 76 94
BIOS_SPI_MUX_S: R375.1 R377.2 U20.1(S) U106.1(OE#) U107.1(OE#) ; also on sheet 180
BIOS_SPI_OE_N: R5846.1 U20.15(OE#)
BMC_SPI_CS: R509.1 U19.6(S) ; also on sheet 180
CLK_32K_SUSCLK_NGFF: R524.1 ; also on sheet 50
CLK_33M_TPM_CONN: CN3.1 ; also on sheet 88
CLK_100M_PE_D_DN: NGFF1.53 ; also on sheet 56
CLK_100M_PE_D_DP: NGFF1.55 ; also on sheet 56
FM_BIOS_RCVR_BOOT_N: JP6.2 R234.2 ; also on sheet 90
FM_LA_TRIGGER_N_PLD_TDO: CN47.2 R918.2 ; also on sheet 90
FM_ME_CMM_N: R260.2 ; also on sheet 90
FM_ME_RCVR_N: JP4.2 R240.2 ; also on sheet 90
FM_MGPIO14: TP316.1 ; also on sheet 166
FM_MGPIO15: TP284.1 ; also on sheet 166
FM_MGPIO16: TP317.1 ; also on sheet 166
FM_MGPIO17: TP315.1 ; also on sheet 166
FM_PASSWORD_CLEAR_N: R241.2 R243.1 ; also on sheet 90
FM_PMBUS_ALERT_BUF_EN: TP283.1 ; also on sheet 52 166
FM_QPI_SLOW_MODE_N: R233.2 R236.1 ; also on sheet 90
IRQ_LVC3_WAKE_N: R1258.1 R1268.1 ; also on sheet 64 74 88 94 95 168
IRQ_LVC3_WAKE_N_MSATA: MSATA1.1 R1268.2
IRQ_LVC3_WAKE_N_NGFF: NGFF1.54 R1258.2
IRQ_SERIAL: CN3.12 ; also on sheet 52 74 91
JTAG_PLD_TDO: CN47.1 ; also on sheet 50 51
LPC_FRAME_N: CN3.7 ; also on sheet 52 74 90
LPC_LAD0: CN3.3 ; also on sheet 74 90
LPC_LAD1: CN3.4 ; also on sheet 74 90
LPC_LAD2: CN3.5 ; also on sheet 74 90
LPC_LAD3: CN3.6 ; also on sheet 74 90
MSATA_LED_N: MSATA1.49 ; also on sheet 91
MSATA_SSD_PRSNT_N: MSATA1.51 ; also on sheet 91
NGFF_LED_N: NGFF1.10 ; also on sheet 91
P2E_WBG_NGFF_RX_C_DN_1: R1208.2 ; also on sheet 92
P2E_WBG_NGFF_RX_C_DN_2: NGFF1.29 ; also on sheet 92
P2E_WBG_NGFF_RX_C_DN_3: NGFF1.17 ; also on sheet 92
P2E_WBG_NGFF_RX_C_DN_4: NGFF1.5 ; also on sheet 92
P2E_WBG_NGFF_RX_C_DP_1: R1207.2 ; also on sheet 92
P2E_WBG_NGFF_RX_C_DP_2: NGFF1.31 ; also on sheet 92
P2E_WBG_NGFF_RX_C_DP_3: NGFF1.19 ; also on sheet 92
P2E_WBG_NGFF_RX_C_DP_4: NGFF1.7 ; also on sheet 92
P2E_WBG_NGFF_TX_C_DN_1: NGFF1.47 R1109.1 ; also on sheet 92
P2E_WBG_NGFF_TX_C_DN_2: NGFF1.35 ; also on sheet 92
P2E_WBG_NGFF_TX_C_DN_3: NGFF1.23 ; also on sheet 92
P2E_WBG_NGFF_TX_C_DN_4: NGFF1.11 ; also on sheet 92
P2E_WBG_NGFF_TX_C_DP_1: NGFF1.49 R1106.1 ; also on sheet 92
P2E_WBG_NGFF_TX_C_DP_2: NGFF1.37 ; also on sheet 92
P2E_WBG_NGFF_TX_C_DP_3: NGFF1.25 ; also on sheet 92
P2E_WBG_NGFF_TX_C_DP_4: NGFF1.13 ; also on sheet 92
PD_BIOS_RCVR_BOOT_N: JP6.3 R237.1
PD_ME_RCVR_BOOT: JP4.1 TP191.1
PD_ME_RCVR_N: JP4.3 R242.1
PD_RST_RTCRST_N: JP3.3 R244.1
PD_SPI_HEADER: R314.1 R730.1
PEDET_SEL: NGFF1.69 R1041.1
PMU_SUS_CLK_NGFF: NGFF1.68 R524.2
PU_RST_RTCRST_N: C272.1 JP3.1 R239.2
RST_BMC_NIC_LRESET_LVC3_R_N: CN3.2 R1274.1 R1275.1
RST_PCIE_PCH_DEV_N: R530.1 ; also on sheet 51 64 74
RST_PCIE_PCH_DEV_N_R: NGFF1.50 R530.2
RST_PLTRST_BUF_N: R1275.2 ; also on sheet 51 52 177
RST_RTCRST_N: JP3.2 R245.1 ; also on sheet 90
RST_SRTCRST_N: C273.1 R246.2 ; also on sheet 90
SATA4_TX_DN: R1038.1 R1109.2 ; also on sheet 91
SATA4_TX_DN_R: MSATA1.31 R1038.2
SATA4_TX_DP: R947.1 R1106.2 ; also on sheet 91
SATA4_TX_DP_R: MSATA1.33 R947.2
SATA5_RX_C_DN: C737.1 SATA1.3
SATA5_RX_C_DP: C738.1 SATA1.2
SATA5_TX_C_DN: C740.2 ; also on sheet 91
SATA5_TX_C_DP: C739.2 ; also on sheet 91
SATA5_TX_CC_DN: C740.1 SATA1.5
SATA5_TX_CC_DP: C739.1 SATA1.6
SATA6G_P4_RX_C_DN: C754.1 MSATA1.25
SATA6G_P4_RX_C_DP: C753.1 MSATA1.23
SATA6G_P4_RX_DN: C754.2 C758.1 ; also on sheet 91
SATA6G_P4_RX_DN_NGFF: C758.2 NGFF1.43 R1207.1
SATA6G_P4_RX_DP: C753.2 C757.1 ; also on sheet 91
SATA6G_P4_RX_DP_NGFF: C757.2 NGFF1.41 R1208.1
SATA6G_P5_RX_DN: C737.2 ; also on sheet 91
SATA6G_P5_RX_DP: C738.2 ; also on sheet 91
SPI_BMCOUT_CLK: R376.1 U20.3(1B2) ; also on sheet 180
SPI_BMCOUT_CS0_N: R373.1 R948.2 U20.6(2B2) ; also on sheet 180
SPI_BMCOUT_MOSI: R427.1 U20.10(3B2) ; also on sheet 180
SPI_DEDIPROG_DQ2: R729.2 U107.4(Y)
SPI_DEDIPROG_DQ3: R313.1 U106.4(Y)
SPI_PCH_CLK: R304.2 R309.2 R376.2 R772.2 U20.4(1A)
SPI_PCH_CLK_R: R304.1 U20.2(1B1) ; also on sheet 90
SPI_PCH_CS0_N: R801.2 U19.3(B0)
SPI_PCH_CS0_N_R: R500.2 R801.1 SKT2.7
SPI_PCH_CS0_R_N: R301.1 U20.5(2B1) ; also on sheet 90
SPI_PCH_CS1_N: R800.2 U19.1(B1)
SPI_PCH_CS1_N_R: R434.2 R800.1 U28.7(CS#)
SPI_PCH_CS_N: R301.2 R373.2 U19.4(A) U20.7(2A)
SPI_PCH_IO2_R: U107.2(A) ; also on sheet 89
SPI_PCH_IO3_R: U106.2(A) ; also on sheet 89
SPI_PCH_MISO: R306.2 R311.2 R432.2 R795.2 U20.12(4A)
SPI_PCH_MISO_R: R306.1 U20.14(4B1) ; also on sheet 90
SPI_PCH_MOSI: R305.2 R310.2 R427.2 R794.2 U20.9(3A)
SPI_PCH_MOSI_R: R305.1 U20.11(3B1) ; also on sheet 90
SPI_SKT0_CLK_R: R309.1 U28.16(CLK)
SPI_SKT0_CLK_R1: R772.1 SKT2.16
SPI_SKT0_HLD_R1_N: R414.2 SKT2.1
SPI_SKT0_HLD_R_N: R308.2 R313.2 U28.1(HOLD#/IO3)
SPI_SKT0_MISO_R: R311.1 U28.8(DO/IO1)
SPI_SKT0_MISO_R1: R795.1 SKT2.8
SPI_SKT0_MOSI_R: R310.1 U28.15(DI/IO0)
SPI_SKT0_MOSI_R1: R794.1 SKT2.15
SPI_SKT0_RESET_N: R464.2 U28.3(RESET#)
SPI_SKT0_WP_N: R312.1 R729.1 R730.2
SPI_SKT0_WP_R1_N: R412.2 SKT2.9
SPI_SKT0_WP_R_N: R307.2 R312.2 U28.9(WP#/IO2)
SPI_SKT2_RESET_N: R466.2 SKT2.3
SYS_BMCOUT_MISO: R432.1 U20.13(4B2) ; also on sheet 180
TPM_PRSNT_N: CN3.10 ; also on sheet 91

Not connected (* = marked no-connect by the designer): CN3 8* 11* 15* NP1* NP2*; JP6 1*; MSATA1 3* 5* 6* 7* 8* 10* 11* 12* 13* 14* 16* 17* 19* 20* 22* 28* 30* 32* 36* 38* 42* 44* 45* 46* 47* 48* NP1* NP2*; NGFF1 6* 8* 20* 22* 24* 26* 28* 30* 32* 34* 36* 38* 40* 42* 44* 46* 48* 52* 56* 58* 67* NP1* NP2*; SKT2 4* 5* 6* 11* 12* 13* 14*; U28 4(NC#4)* 5(NC#5)* 6(NC#6)* 11(NC#11)* 12(NC#12)* 13(NC#13)* 14(NC#14)*

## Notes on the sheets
sheet 78
- TPM HEADER
sheet 79
- WELLSBURG SPI FLASH
- CAD NOTE:
  MARK SILKSCREEN FOR BIOS CHIP AS
  PRIMARY   BIOS/FW SOCKET - 0
- CAD NOTE:
  PLACE CAPACITORS AS CLOSE
  AS POSSIBLE TO SKT POWER PINS
- CAD NOTE:
  PLACE SERIES RESISTORS
  NEAR PCH WITHIN 500 MIL
- FAB2 REV001 20150617
- From PCH
- From PCH
- CAD NOTE:
  PLACE ALL SERIES RESISTORS
  EXCEPT MISO R NEAR WBG < 0.5"
  AND MISO R NEAR SPI < 0.5"
- 64.10015.L1L
- From PCH
- BOM NOTE:
  16MB  BIOS  SPI  -  VENDOR:   WINBOND   -  MPN:  W25Q128FVFIG
- From PCH
- FAB1 REV013 20150413
- Change to 73.03157.D0H
- NORMAL: QUAD MODE
- 1-2 (DEFAULT)
- PCH SPI IO2
- 2-3
- FORCE WRITE PROTECT
- E
- S
- 1A
- 2A
- 3A
- 4A
- Function
- H
- X
- Hi-Z
- Hi-Z
- Hi-Z
- Hi-Z
- Disable
- Input (S)
- Function
- L
- L
- 1B1
- 2B1
- 3B1
- 4B1
- S = 0
- L
- B0 Connected to A
- L
- H
- 1B2
- 2B2
- 3B2
- 4B2
- S = 1
- H
- B1 Connected to A
sheet 80
- miniSAS CONNECTORS_SATA_PWR
- FAB1 20150126
- FAB1 REV006 20150324
- FAB1 REV005 20150323
- FAB1 REV008 20150326
sheet 81
- mSATA CONNECTOR
- FAB1 REV005 20150322
- FAB1 REV005 20150323
- FAB1 REV005 20150323
sheet 82
- SATA CONNECTORS
- SATA0
- Place cap. close to chip within 0.25 inch.
- CONTROLLER
  SIDE
- Change to 20.81112.007
- FAB1 REV012 20150409
- Pin 1
- Pin 4
- FAB1 REV001 20150316
sheet 83
- NGFF CONNECTOR
- mSATA and M.2 connector co-layout
- NC:PCI-E
  GND:SATA
- FAB2 REV001 20150625
- FAB1 REV005 20150323
- FAB1 REV017 20150419
- FAB1 REV011 20150407
- Location
- mSATA BOM
- M.2 BOM (PCIe)
- M.2 BOM (SATA)
- R947, R1038, R1268
- POP
- NOPOP
- NOPOP
- C310, C311, C312, C313
- POP
- NOPOP
- NOPOP
- C753, C754
- POP
- NOPOP
- NOPOP
- FAB1 REV004 20150320
- MSATA1
- POP
- NOPOP
- NOPOP
- C755, C756, C757, C758
- POP
- NOPOP
- POP
- Remove components
- R1106, R1109
- NOPOP
- NOPOP
- POP
- R1041
- NOPOP
- NOPOP
- POP
- R1207, R1208, R1230
- R1239, R1240, R1243
- NOPOP
- POP
- NOPOP
- R1244, R1248
- C280, C284, C285, C286
- NOPOP
- POP
- NOPOP
- C287, C288, C289, C290
- R524, R530 ,R1258
- NOPOP
- POP
- POP
- NGFF1
- NOPOP
- POP
- POP
sheet 84
- WELLSBURG - HEADERS
- QPI SLOW MODE SELECT
- BIOS RECOVERY MODE JUMPER
- FAB1 REV005 20150322
- POP R233
- QPI FAST MODE (DEFAULT)
- Remove redundant components.
- POP R236
- QPI SLOW MODE (66MT/S)
- R233
- DMI TX TERMINATION WHEN DC-COUPLED MODE:
  '0': DMI TX IS TERMINATED TO VSS
  '1': DMI TX IS TERMINATED TO VCC
  INTERNAL PULL-DOWN (9K-50K) WHEN OPERATING IN AC-COUPLED
  MODE THIS STRAP HAS NOT EFECT ON TX TERMINATION.
- POP R234
- NORMAL (DEFAULT)
- POP R237
- R234
- RECOVER BIOS
- ME FIRMWARE UPDATE
- PASSWORD CLEAR JUMPER
- CMOS CLEAR JUMPER
- POP R241
- NORMAL (DEFAULT)
- 1-2
- NORMAL (DEFAULT)
- POP R241
- PASSWORD CLEAR
- 1-2
- NORMAL RTC RESET (DEFAULT)
- R243
- 2-3
- ME FORCE UPDATE
- 2-3
- CLEAR RTC REGISTERS
- CMM COMMUNICATION JUMPER
- MGPIO HEADER
- STORAGE SV TRIGGER
- FAB1 20150310
- 1 - 2
- CPLD PROGRAMMING
- Place it with order
- 2 - 3
- LA TRIGGER
- FAB1 REV005 20150322
- POP R259
- NORMAL<DEFAULT>
- POP R260
- CMM NOTIFICATION
sheet 85
- WELLSBURG - FILTERING
sheet 86
- WELLSBURG - GROUND
